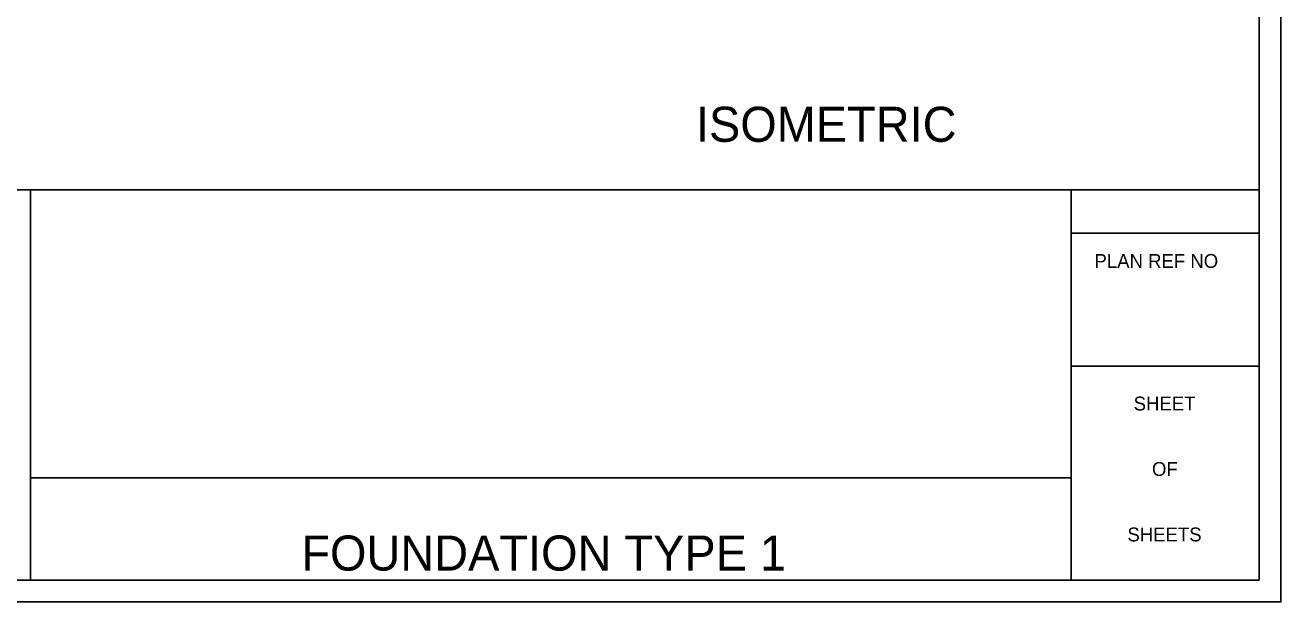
# Model space of a CAD drawing. Extents: x 99888 to 103177, y 100000 to 102076.
# Drawn here: x 102434 to 103150, y 100000 to 100329 of the extents above; entities that cross this region are included whole.
import ezdxf

# ---------------------------------------------------------------- set-up
doc = ezdxf.new("R2010")
doc.units = 0
for name, color, linetype in [('Level 20', 7, 'Continuous'), ('SH_GI_PlotLimits', 7, 'Continuous'), ('SH_GI_SheetBorder', 7, 'Continuous'), ('SH_GI_SheetTextInCells', 7, 'Continuous')]:
    doc.layers.add(name, color=color, linetype=linetype)

msp = doc.modelspace()

# ---------------------------------------------------------------- linework, layer by layer
at = {"layer": 'SH_GI_PlotLimits'}
msp.add_lwpolyline([(99888.5, 100000), (103150, 100000), (103150, 102075.5), (99888.5, 102075.5)], close=True, dxfattribs=at)
msp.add_lwpolyline([(99888.5, 100000), (103150, 100000), (103150, 102075.5), (99888.5, 102075.5)], close=True, dxfattribs=at)
at = {"layer": 'SH_GI_SheetBorder'}
for p, q in [((103137.64, 102063.15), (103137.64, 100012.35)), ((103137.64, 102063.15), (103137.64, 100012.35)), ((100024.39, 100234.91), (103137.64, 100234.91)), ((100024.39, 100234.91), (103137.64, 100234.91)), ((102437.01, 100234.91), (102437.01, 100012.35)), ((102437.01, 100234.91), (102437.01, 100012.35)), ((103030.48, 100234.91), (103030.48, 100012.35)), ((103030.48, 100234.91), (103030.48, 100012.35)), ((103030.48, 100210.18), (103137.64, 100210.18)), ((103030.48, 100210.18), (103137.64, 100210.18)), ((103030.48, 100134.44), (103137.64, 100134.44)), ((103030.48, 100134.44), (103137.64, 100134.44)), ((102437.01, 100070.76), (103030.48, 100070.76)), ((102437.01, 100070.76), (103030.48, 100070.76)), ((100024.39, 100012.35), (103137.64, 100012.35)), ((100024.39, 100012.35), (103137.64, 100012.35))]:
    msp.add_line(p, q, dxfattribs=at)

# ---------------------------------------------------------------- texts
at = {"layer": 'Level 20'}
for s, p in [('ISOMETRIC', (102816.46, 100262.3)), ('FOUNDATION TYPE 1', (102591.44, 100017.84))]:
    msp.add_text(s, height=20, dxfattribs=at).set_placement(p)
at = {"layer": 'SH_GI_SheetBorder'}
msp.add_text('PLAN REF NO', height=7.913, dxfattribs=at).set_placement((103043.69, 100190.41))
msp.add_text('PLAN REF NO', height=7.913, dxfattribs=at).set_placement((103043.69, 100190.41))
at = {"layer": 'SH_GI_SheetTextInCells'}
for s, p in [('SHEET', (103066.03, 100109.13)), ('SHEET', (103066.03, 100109.13)), ('OF', (103076.49, 100071.81)), ('OF', (103076.49, 100071.81)), ('SHEETS', (103062.48, 100034.48)), ('SHEETS', (103062.48, 100034.48))]:
    msp.add_text(s, height=7.913, dxfattribs=at).set_placement(p)

doc.saveas('drawing.dxf')
